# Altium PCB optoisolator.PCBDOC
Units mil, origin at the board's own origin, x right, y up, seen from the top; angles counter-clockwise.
Board outline 6000 x 4000 mil, 2 copper layers (Top Layer, Bottom Layer); 22 components, 16 nets, 52 pads, 0 vias.
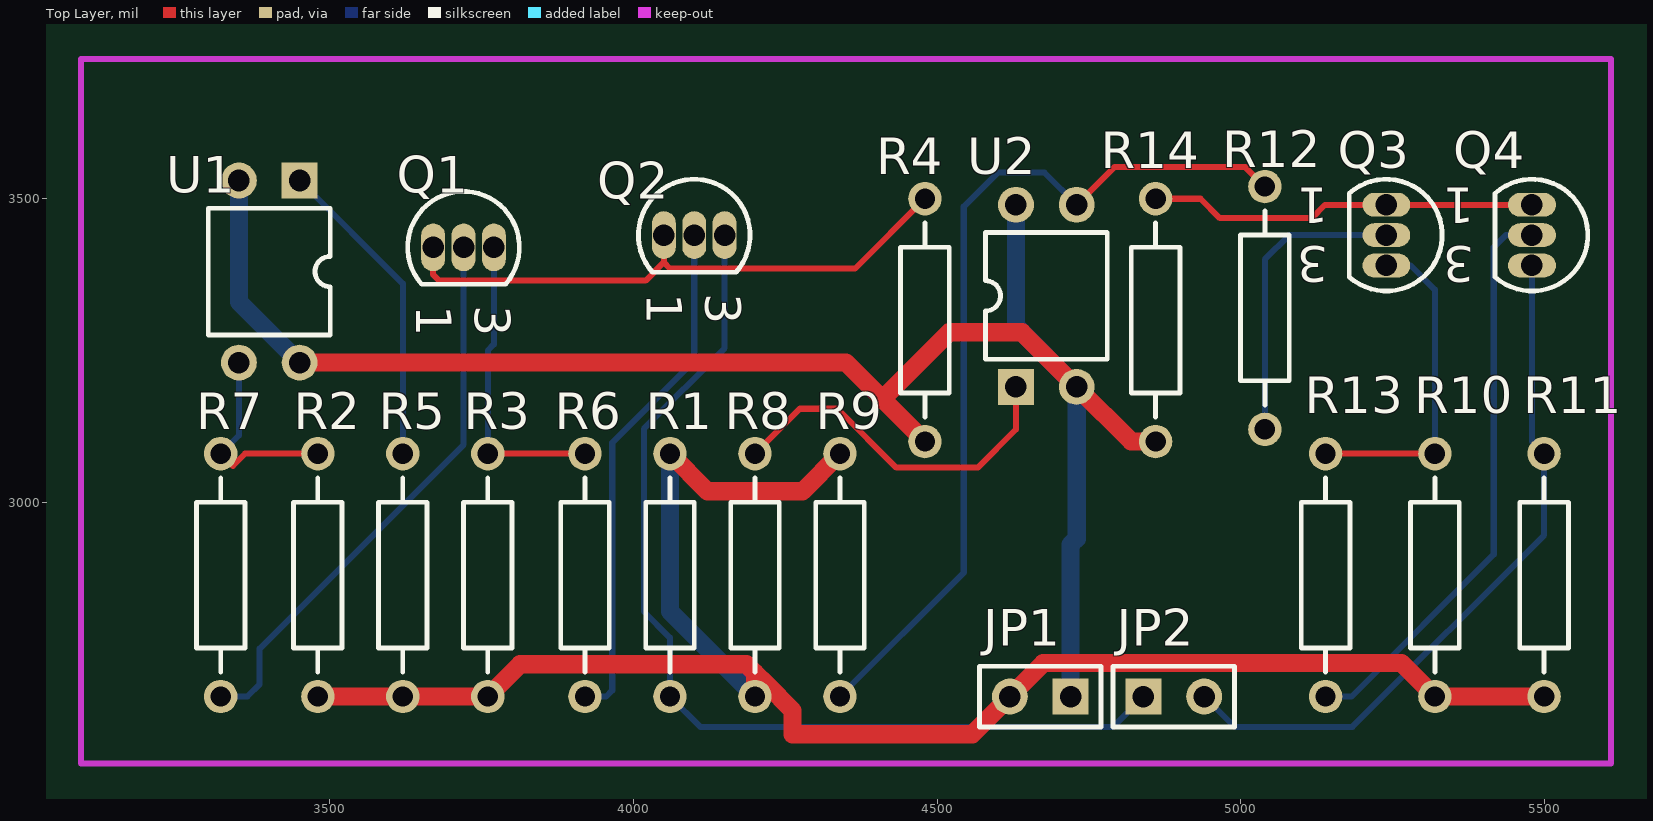
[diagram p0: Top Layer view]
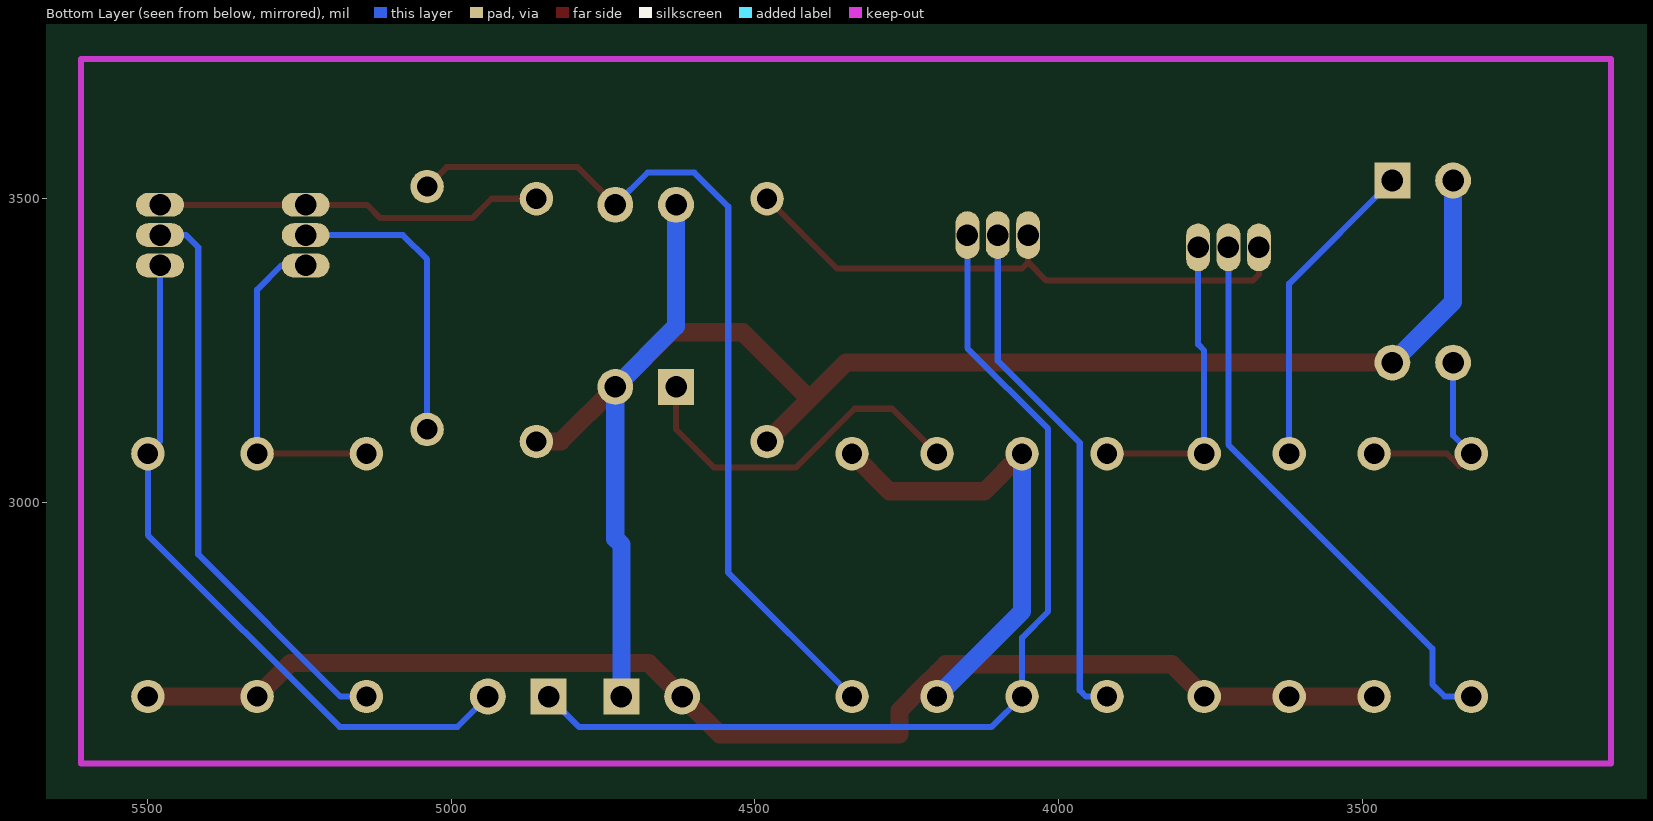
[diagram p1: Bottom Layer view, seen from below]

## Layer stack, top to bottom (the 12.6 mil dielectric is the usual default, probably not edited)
Top Layer: signal copper 1.4
Dielectric: dielectric 12.6, FR-4, Dk 4.8
Bottom Layer: signal copper 1.4

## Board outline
1000,1000 7000,1000 7000,5000 1000,5000

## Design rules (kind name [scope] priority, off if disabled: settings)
Clearance [All] p1: gap=10
ComponentClearance [All] p1: gap=10 collisioncheckmode=0
PolygonConnect [All] p1: connectstyle=Relief reliefconductorwidth=10 reliefentries=4 polygonreliefangle="90 Angle"
RoutingLayers [All] p1: top layer=Horizontal bottom layer=Vertical
RoutingVias [All] p1: holewidth=28 width=50 viastyle="Through Hole" minholewidth=28 minwidth=50 maxholewidth=28 maxwidth=50
SolderMaskExpansion [All] p1: expansion=4
TestPointUsage [All] p1: valid=0 allowmultiple=FALSE
Testpoint [All] p1: side=15 testpointundercomponent=TRUE minsize=40 maxsize=100 preferedsize=60 minholesize=0 maxholesize=40 preferedholesize=32 testpointgrid=1 style=1023 order=1234567890
Width Width_2 [InNet('GND')] p1: maxlimit=50 minlimit=10 preferedwidth=30
Width Width_1 [InNet('+5V')] p2: maxlimit=50 minlimit=10 preferedwidth=30
Width [All] p3: maxlimit=50 minlimit=10 preferedwidth=10
16 further rules are at their usual default settings.

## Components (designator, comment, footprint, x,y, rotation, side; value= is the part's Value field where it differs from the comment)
JP1 "Header 2" HDR1X2 4720,2680 r180 top
JP2 "Header 2" HDR1X2 4840,2680 r0 top
Q1 "2N4401" BCY-W3/D4.7 3720,3420 r270 top
Q2 "2N4401" BCY-W3/D4.7 4100,3440 r270 top
Q3 "2N4401" BCY-W3/D4.7 5240,3440 r180 top
Q4 "2N4401" BCY-W3/D4.7 5480,3440 r180 top
R1 "Res2" AXIAL-0.4 4060,2880 r90 top
R2 "10K" AXIAL-0.4 3480,2880 r270 top
R3 "Res2" AXIAL-0.4 3760,2880 r270 top
R4 "Res2" AXIAL-0.4 4480,3300 r90 top
R5 "Res2" AXIAL-0.4 3620,2880 r270 top
R6 "Res2" AXIAL-0.4 3920,2880 r270 top
R7 "Res2" AXIAL-0.4 3320,2880 r270 top
R8 "Res2" AXIAL-0.4 4200,2880 r270 top
R9 "10K" AXIAL-0.4 4340,2880 r90 top
R10 "Res2" AXIAL-0.4 5320,2880 r270 top
R11 "Res2" AXIAL-0.4 5500,2880 r270 top
R12 "Res2" AXIAL-0.4 5040,3320 r270 top (schematic designator RR12)
R13 "Res2" AXIAL-0.4 5140,2880 r270 top
R14 "Res2" AXIAL-0.4 4860,3300 r90 top
U1 "Optoisolator1" DIP-4 3400,3380 r180 top
U2 "Optoisolator1" DIP-4 4680,3340 r0 top

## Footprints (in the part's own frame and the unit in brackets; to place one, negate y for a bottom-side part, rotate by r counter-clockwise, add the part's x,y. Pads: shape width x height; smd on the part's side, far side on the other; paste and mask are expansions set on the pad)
AXIAL-0.4 [mm]
  round 1.4 hole 0.85: 1(-5.08,0) 2(5.08,0)
  silkscreen extent -4.06,-1.02 4.06,1.02
BCY-W3/D4.7 [mm]
  oval 2x1 hole 0.9: 1(0,-1.27) 2(0,0) 3(0,1.27)
  silkscreen extent -2.33,-2.33 1.55,2.33
DIP-4 [mm]
  rect 1.5x1.5 hole 0.9: 1(-1.27,-3.81)
  round 1.5 hole 0.9: 2(1.27,-3.81) 3(1.27,3.81) 4(-1.27,3.81)
  silkscreen extent -2.55,-2.65 2.55,2.65
HDR1X2 [mm]
  rect 1.5x1.5 hole 0.9: 1(0,0)
  round 1.5 hole 0.9: 2(2.54,0)
  silkscreen extent -1.27,-1.27 3.81,1.27

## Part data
JP1 JP2: "Header, 2-Pin"
Q1 Q2 Q3 Q4: "NPN General Purpose Amplifier"
R1 R3 R4 R5 R6 R7 R8 R10 R11 R12 R13 R14: "Resistor"
R2 R9: library part Res2, "Resistor"
U1 U2: "Optoisolator"

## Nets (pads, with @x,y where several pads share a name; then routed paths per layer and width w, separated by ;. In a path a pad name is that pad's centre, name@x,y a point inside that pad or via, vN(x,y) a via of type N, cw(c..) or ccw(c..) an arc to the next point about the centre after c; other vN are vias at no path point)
+5V: JP1.2 R1.2 R2.2 R3.2 R5.2 R8.2 R9.2 R10.2 R11.2 | length 3012
  Top Layer w30: R2.2 R5.2 R3.2 3813,2733 4186,2733 4200,2719 ; R1.2 4122,3018 4278,3018 R9.2 ; R8.2 4200,2719 ; R11.2 R10.2 5265,2735 4675,2735 JP1.2 4558,2618 4262,2618 4262,2657 4219.5,2699.5 4200,2719
  Bottom Layer w30: R1.2 4060,2820 R8.2
GND: JP1.1 R4.1 R14.1 U1.2 U1.4 U2.2 U2.4 | length 2851
  Top Layer w30: U1.4 4350,3230 4410,3170 ; R4.1 4410,3170 ; R14.1 4820,3100 U2.2 4640,3280 4520,3280 4410,3170
  Bottom Layer w30: U1.2 3350,3330 U1.4 ; U2.4 4630,3290 U2.2 4730,2940 4720,2930 JP1.1
NetJP2_1: JP2.1 Q2.3 R1.1 | length 1654.3
  Bottom Layer w10: Q2.3 4150,3254 4017,3121 4017,2820 4060,2777 R1.1 4110,2630 4790,2630 JP2.1
NetJP2_2: JP2.2 Q4.3 R11.1 | length 1163.9
  Bottom Layer w10: JP2.2 4990,2630 5184,2630 5500,2946 R11.1 5480,3100 Q4.3
NetQ1_1: Q1.1 Q2.1 R4.2 | length 968.3
  Top Layer w10: Q1.1 3670,3375 3680,3365 4020,3365 4050,3395 ; Q2.1 4050,3395 ; R4.2 4365,3385 4060,3385 4050,3395
NetQ1_2: Q1.2 R7.2 | length 931.5
  Bottom Layer w10: R7.2 3364,2680 3384,2700 3384,2759 3720,3095 Q1.2
NetQ1_3: Q1.3 R3.1 R6.1 | length 504.1
  Top Layer w10: R3.1 R6.1
  Bottom Layer w10: R3.1 3760,3250 3770,3260 Q1.3
NetQ2_2: Q2.2 R6.2 | length 855.1
  Bottom Layer w10: R6.2 3955,2680 3965,2690 3965,3098 4100,3233 Q2.2
NetQ3_1: Q3.1 Q4.1 R14.2 | length 642.4
  Top Layer w10: R14.2 4934,3500 4966,3468 5117,3468 5139,3490 Q3.1 Q4.1
NetQ3_2: Q3.2 R12.2 | length 496.6
  Bottom Layer w10: R12.2 5040,3400 5080,3440 Q3.2
NetQ3_3: Q3.3 R10.1 R13.1 | length 546.6
  Top Layer w10: R13.1 R10.1
  Bottom Layer w10: Q3.3 5280,3390 5320,3350 R10.1
NetQ4_2: Q4.2 R13.2 | length 951.2
  Bottom Layer w10: R13.2 5183,2680 5417,2914 5417,3420 5437,3440 Q4.2
NetR2_1: R2.1 R7.1 U1.3 | length 339
  Top Layer w10: R7.1 3340,3060 3360,3080 R2.1
  Bottom Layer w10: R7.1 3350,3110 U1.3
NetR5_1: R5.1 U1.1 | length 520.4
  Bottom Layer w10: U1.1 3620,3360 R5.1
NetR8_1: R8.1 U2.1 | length 596.9
  Top Layer w10: R8.1 4274,3154 4336,3154 4433,3057 4567,3057 4630,3120 U2.1
NetR9_1: R9.1 R12.1 U2.3 | length 1471.6
  Top Layer w10: U2.3 4792,3552 5008,3552 R12.1
  Bottom Layer w10: R9.1 4544,2884 4544,3487 4600,3543 4677,3543 U2.3

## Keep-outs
Keep-Out Layer:
  lines w10: 3090,2570 5610,2570 5610,3730 3090,3730 3090,2570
